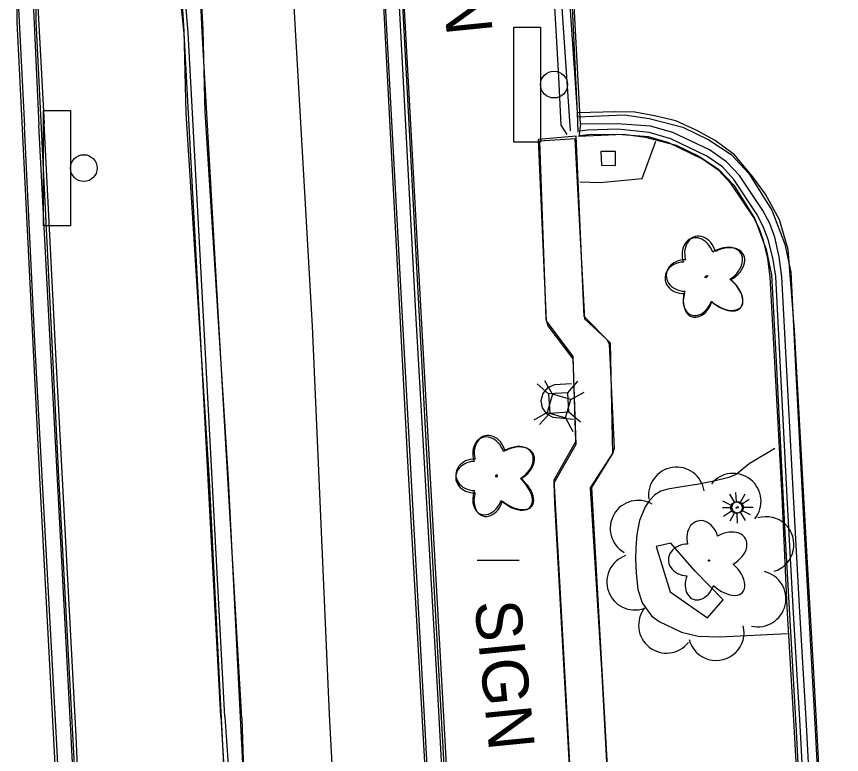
# Model space of a CAD drawing. Extents: x 588843 to 2552415, y 180129 to 269402.
# Drawn here: x 594718.3 to 594826, y 184696.5 to 184792.7 of the extents above; entities that cross this region are included whole.
import ezdxf

# ---------------------------------------------------------------- set-up
doc = ezdxf.new("R2010")
doc.units = 0
for name, color, linetype in [('Default', 7, 'Continuous'), ('E_DWY', 7, 'Continuous'), ('E_LAND_ShrubLine', 7, 'Continuous'), ('E_LAND_TreeLine_P', 7, 'Continuous'), ('E_LAND_Vegetation', 7, 'Continuous'), ('E_LTG', 7, 'Continuous'), ('E_MISCPROP_Planter', 7, 'Continuous'), ('E_PATH_Sidewalk', 7, 'Continuous'), ('E_RDWY_AsphConc', 7, 'Continuous'), ('E_RDWY_C_and_G', 7, 'Continuous'), ('E_RDWY_PavtEdge', 7, 'Continuous'), ('E_SGN', 7, 'Continuous'), ('E_SGN_Text', 7, 'Continuous'), ('E_STRUCT', 7, 'Continuous'), ('E_UTL_AG_Bold', 7, 'Continuous'), ('E_WAL', 7, 'Continuous')]:
    doc.layers.add(name, color=color, linetype=linetype)

# ---------------------------------------------------------------- blocks, each defined once
blk = doc.blocks.new('PED')
at = {"layer": 'Default'}
for p, q in [((-2.5, 2.5), (-5.33, 5.33)), ((2.5, 2.5), (5.33, 5.33)), ((-2.5, -2.5), (-5.33, -5.33)), ((2.5, -2.5), (5.33, -5.33))]:
    blk.add_line(p, q, dxfattribs=at)
blk.add_lwpolyline([(-2.5, -2.5), (2.5, -2.5), (2.5, 2.5), (-2.5, 2.5)], close=True, dxfattribs=at)
blk = doc.blocks.new('LPOL')
at = {"layer": 'Default'}
for p, q in [((-0.75, 1.3), (-2, 3.46)), ((0.75, 1.3), (2, 3.46)), ((-4, 0), (-1.5, 0)), ((1.5, 0), (4, 0)), ((-2, -3.46), (-0.75, -1.3)), ((2, -3.46), (0.75, -1.3))]:
    blk.add_line(p, q, dxfattribs=at)
for radius in [1.5, 1.5, 1.5, 0.125]:
    blk.add_circle((0, 0), radius, dxfattribs=at)
blk = doc.blocks.new('SGN_1')
at = {"layer": 'Default'}
blk.add_lwpolyline([(-3.5, -15), (-10.5, -15), (-10.5, 15), (-3.5, 15)], close=True, dxfattribs=at)
blk.add_circle((0, 0), 3.5, dxfattribs=at)
blk = doc.blocks.new('DTRE_1_1')
at = {"layer": 'Default'}
blk.add_circle((-0.18, 0), 0.183, dxfattribs=at)
for centre, major_axis, ratio in [((-1.87, 5.32), (1.36, -4.98), 0.782863), ((4.06, 2.74), (-5.27, -2.93), 0.691916), ((-5.87, 0.15), (4.93, -0.12), 0.832022), ((3.54, -3.71), (-5.01, 4.58), 0.560249), ((-2.49, -5.24), (1.8, 4.86), 0.716896)]:
    blk.add_ellipse(centre, major_axis=major_axis, ratio=ratio, start_param=1.570796, end_param=4.712389, dxfattribs=at)
blk = doc.blocks.new('LPOL_4')
at = {"layer": 'E_LTG'}
for p, q in [((-2.46, 4.26), (-6.56, 11.36)), ((2.46, 4.26), (6.56, 11.36)), ((-13.12, 0), (-4.92, 0)), ((4.92, 0), (13.12, 0)), ((-6.56, -11.36), (-2.46, -4.26)), ((6.56, -11.36), (2.46, -4.26))]:
    blk.add_line(p, q, dxfattribs=at)
for radius in [4.92, 4.92, 4.92, 0.41]:
    blk.add_circle((0, 0), radius, dxfattribs=at)
blk = doc.blocks.new('DTRE_4')
at = {"layer": 'E_LAND_Vegetation'}
blk.add_circle((-0.6, 0), 0.601, dxfattribs=at)
for centre, major_axis, ratio in [((-6.14, 17.45), (4.46, -16.34), 0.782863), ((13.31, 8.98), (-17.3, -9.61), 0.691916), ((-19.26, 0.5), (16.18, -0.4), 0.832022), ((11.62, -12.16), (-16.44, 15.03), 0.560249), ((-8.18, -17.2), (5.91, 15.93), 0.716896)]:
    blk.add_ellipse(centre, major_axis=major_axis, ratio=ratio, start_param=1.570796, end_param=4.712389, dxfattribs=at)
blk = doc.blocks.new('PED_3')
at = {"layer": 'E_UTL_AG_Bold'}
for p, q in [((-8.2, 8.2), (-17.48, 17.48)), ((8.2, 8.2), (17.48, 17.48)), ((-8.2, -8.2), (-17.48, -17.48)), ((8.2, -8.2), (17.48, -17.48))]:
    blk.add_line(p, q, dxfattribs=at)
blk.add_lwpolyline([(-8.2, -8.2), (8.2, -8.2), (8.2, 8.2), (-8.2, 8.2)], close=True, dxfattribs=at)
blk = doc.blocks.new('SIGN_3')
at = {"layer": 'E_SGN'}
blk.add_text('SIGN', height=39.37, dxfattribs=at).set_placement((-56.13, -19.68))

msp = doc.modelspace()

# ---------------------------------------------------------------- linework, layer by layer
at = {"layer": 'E_DWY'}
for points in [[(594789.01, 184816.25), (594791.51, 184779.58)], [(594823.35, 184688.72), (594822.34, 184707.09), (594821.51, 184721.44), (594820.6, 184737.77), (594819.82, 184751.76), (594819.02, 184762.29), (594817.89, 184766.14), (594816.04, 184769.5), (594814.36, 184771.83), (594812.01, 184774.62), (594809.49, 184776.51), (594807.01, 184777.85), (594804.36, 184779.07), (594801.57, 184779.74), (594799, 184780.2), (594796.53, 184780.25), (594791.54, 184780.11)], [(594791.51, 184779.58), (594797.65, 184779.85), (594800.87, 184779.39), (594805.25, 184778.25), (594808.67, 184776.58), (594811.56, 184774.69), (594813.89, 184772.2), (594816.89, 184767.41), (594818.56, 184762.99), (594819.34, 184759.34), (594819.97, 184746.98), (594821.08, 184725.47), (594822.5, 184700.4)], [(594791.62, 184777.08), (594797.53, 184777.34), (594800.38, 184776.93), (594804.38, 184775.89), (594807.44, 184774.4), (594809.94, 184772.76), (594811.9, 184770.67), (594814.64, 184766.3), (594816.15, 184762.28), (594816.85, 184759.01), (594817.47, 184746.85), (594818.58, 184725.34), (594820.01, 184700.26)], [(594820, 184700.38), (594821.46, 184672.4), (594823.08, 184639.78), (594823.47, 184632.92)], [(594822.5, 184700.51), (594823.95, 184672.53), (594825.57, 184639.92), (594825.96, 184633.06)]]:
    msp.add_lwpolyline(points, dxfattribs=at)
at = {"layer": 'E_LAND_ShrubLine'}
msp.add_lwpolyline([(594803.68, 184724.02), (594801.79, 184723.59), (594803.6, 184717.65), (594808.47, 184714.29), (594810.51, 184716.6), (594806.82, 184720.4)], close=True, dxfattribs=at)
at = {"layer": 'E_LAND_TreeLine_P'}
for centre, start, end in [((594804.44, 184730.28), 8.6203, 188.6203), ((594811.83, 184729.46), 321.1966, 141.1966), ((594799.44, 184725.95), 59.7491, 239.7491), ((594816.12, 184723.82), 286.7654, 106.7654), ((594798.99, 184718.94), 109.1967, 289.1967), ((594815.07, 184716.75), 256.8004, 76.8004), ((594803.14, 184713.31), 141.7812, 321.7812), ((594809.62, 184712.35), 194.2218, 14.2218)]:
    msp.add_arc(centre, 3.64, start, end, dxfattribs=at)
at = {"layer": 'E_MISCPROP_Planter'}
for points in [[(594791.84, 184771.1), (594794.47, 184771.02), (594799.97, 184771.55), (594801.76, 184776.41)], [(594790.76, 184744.79), (594788.51, 184744.65), (594787.62, 184744.26), (594786.99, 184743.52), (594786.74, 184742.58), (594786.74, 184742.58), (594786.91, 184741.65), (594787.47, 184740.88), (594788.3, 184740.42), (594788.3, 184740.42), (594790.99, 184740.19)], [(594817.26, 184736.35), (594813.94, 184734.33), (594812.23, 184732.98), (594812.23, 184732.98), (594811.28, 184732.56), (594811.28, 184732.56), (594809.32, 184732.1), (594809.32, 184732.1), (594807.34, 184731.69), (594807.34, 184731.69), (594805.13, 184731.36), (594805.13, 184731.36), (594803.29, 184731.06), (594803.29, 184731.06), (594802.41, 184730.77), (594801.63, 184730.29), (594801.63, 184730.29), (594800.9, 184729.59), (594800.34, 184728.76), (594800.34, 184728.76), (594799.6, 184726.97), (594799.6, 184726.97), (594799.26, 184725.12), (594799.26, 184725.12), (594799.15, 184723.45), (594799.15, 184723.45), (594799.11, 184721.96), (594799.11, 184721.96), (594799.17, 184720.09), (594799.17, 184720.09), (594799.41, 184717.96), (594799.41, 184717.96), (594799.97, 184716.22), (594799.97, 184716.22), (594801.16, 184714.55), (594801.16, 184714.55), (594802.17, 184713.78), (594802.17, 184713.78), (594805.1, 184712.42), (594805.1, 184712.42), (594807.28, 184711.87), (594807.28, 184711.87), (594810.09, 184711.79), (594810.09, 184711.79), (594818.91, 184712.24)]]:
    msp.add_lwpolyline(points, dxfattribs=at)
at = {"layer": 'E_PATH_Sidewalk'}
for points in [[(594797.74, 184652.91), (594794.94, 184703.55), (594793.4, 184731.28), (594796.14, 184735.68), (594795.81, 184750.1), (594792.41, 184753.56), (594791.37, 184777.06), (594786.45, 184776.63)], [(594792.8, 184652.96), (594790.08, 184703.35), (594788.47, 184732.25), (594791.3, 184737.24), (594790.98, 184748.34), (594787.5, 184752.99), (594786.45, 184776.63)], [(594791.25, 184776.72), (594786.56, 184776.42), (594787.4, 184753.25), (594787.66, 184752.35), (594790.93, 184748.04), (594791.31, 184736.87), (594788.45, 184731.85), (594788.53, 184729.27), (594790.77, 184688.8), (594793.22, 184643.35), (594794.8, 184614.59)], [(594791.18, 184776.71), (594792.42, 184753.24), (594795.34, 184750.57), (594795.67, 184749.96), (594796.29, 184736.37), (594796.13, 184735.8), (594793.18, 184731.22), (594794.7, 184706.82), (594797.33, 184658.05), (594799.1, 184624.16), (594799.83, 184613.6)]]:
    msp.add_lwpolyline(points, dxfattribs=at)
at = {"layer": 'E_RDWY_AsphConc'}
msp.add_lwpolyline([(594791.9, 184778.65), (594790.86, 184798.24), (594790.11, 184817.93)], dxfattribs=at)
msp.add_lwpolyline([(594794.57, 184775.09), (594794.64, 184773.31), (594796.47, 184773.26), (594796.5, 184775.08)], close=True, dxfattribs=at)
at = {"layer": 'E_RDWY_C_and_G'}
for points in [[(594764.27, 184831.13), (594766.46, 184789.1), (594769.36, 184734.71), (594772.55, 184677.72)], [(594766.76, 184831.26), (594768.96, 184789.23), (594771.86, 184734.85), (594775.04, 184677.86)], [(594718.43, 184791.96), (594718.35, 184801.14), (594718.73, 184805.88), (594720.18, 184813.05), (594723.29, 184821.43), (594725.59, 184827.56), (594727.26, 184828.19), (594729.05, 184828.71), (594731.7, 184827.95), (594733.61, 184824.99), (594739.33, 184810.73), (594742.25, 184798.17), (594742.67, 184790.92), (594742.92, 184780.14)], [(594720.93, 184791.98), (594720.85, 184801.05), (594721.21, 184805.53), (594722.59, 184812.36), (594725.63, 184820.55), (594727.54, 184825.62), (594728.05, 184825.82), (594729.05, 184826.11), (594730.11, 184825.8), (594731.38, 184823.83), (594736.94, 184809.98), (594739.76, 184797.81), (594740.17, 184790.82), (594740.42, 184780.08)], [(594777.08, 184633.63), (594775.2, 184633.55), (594774.21, 184652.19), (594771.49, 184702.97), (594768.71, 184753.45), (594765.95, 184803.81)], [(594778.76, 184630.05), (594777.08, 184633.63), (594776.1, 184652.26), (594773.41, 184702.94), (594770.48, 184753.24), (594767.8, 184803.8)], [(594779.34, 184630.27), (594777.65, 184633.73), (594776.77, 184652.29), (594773.99, 184703.02), (594771.16, 184753.32), (594768.38, 184803.92)], [(594747.72, 184701.19), (594744.83, 184751.13), (594742.55, 184790.69), (594742.08, 184801.18)], [(594744.99, 184701.39), (594742.33, 184751.07), (594740.2, 184790.51), (594739.17, 184800.26)], [(594745.54, 184701.35), (594742.89, 184751.17), (594740.76, 184790.55), (594740.21, 184796.97)], [(594718.52, 184795.48), (594719.41, 184778.31)], [(594720.49, 184795.56), (594721.24, 184778.5)], [(594721.06, 184795.63), (594721.96, 184778.71)], [(594724.06, 184683), (594721.37, 184732.51), (594718.42, 184791.96)], [(594726.55, 184683.13), (594723.86, 184732.64), (594720.92, 184792.08)], [(594740.42, 184780.08), (594743.46, 184732.19), (594745.52, 184691.69)], [(594742.92, 184780.24), (594745.96, 184732.33), (594748.01, 184691.82)], [(594724.39, 184682.67), (594723.55, 184698.55), (594720.8, 184749.42), (594719.41, 184778.31)], [(594726.29, 184682.73), (594725.47, 184698.74), (594722.78, 184749.52), (594721.24, 184778.5)], [(594726.83, 184682.74), (594726.13, 184698.83), (594723.43, 184749.56), (594721.96, 184778.71)], [(594823.84, 184653.88), (594821.39, 184700.32), (594820.5, 184715.79), (594819.72, 184730.13), (594818.18, 184758.72), (594817.84, 184761.32), (594817.25, 184763.89), (594817.25, 184763.89), (594816.6, 184765.69), (594815.72, 184767.38), (594815.72, 184767.38), (594812.65, 184771.93), (594812.65, 184771.93), (594810.97, 184773.72), (594810.97, 184773.72), (594808.73, 184775.27), (594808.73, 184775.27), (594803.95, 184777.56), (594803.95, 184777.56), (594801.03, 184778.38), (594801.03, 184778.38), (594796.68, 184778.68), (594796.68, 184778.68), (594791.9, 184778.65), (594791.78, 184777.74), (594791.73, 184777.12)], [(594823.06, 184653.8), (594820.55, 184700.24), (594819.67, 184715.66), (594818.87, 184730.01), (594817.39, 184758.78), (594816.99, 184761.22), (594816.38, 184763.61), (594816.38, 184763.61), (594815.76, 184765.3), (594814.93, 184766.9), (594814.93, 184766.9), (594811.93, 184771.44), (594811.93, 184771.44), (594810.42, 184773.08), (594810.42, 184773.08), (594808.41, 184774.48), (594808.41, 184774.48), (594803.7, 184776.73), (594803.7, 184776.73), (594800.88, 184777.56), (594800.88, 184777.56), (594796.73, 184777.98), (594796.73, 184777.98), (594792.82, 184777.84), (594791.78, 184777.74)], [(594822.37, 184653.72), (594819.8, 184700.18), (594818.89, 184715.65), (594818.21, 184730.08), (594816.65, 184758.75), (594816.34, 184761.12), (594815.81, 184763.45), (594815.81, 184763.45), (594815.23, 184765.07), (594814.45, 184766.6), (594814.45, 184766.6), (594811.56, 184770.87), (594811.56, 184770.87), (594809.95, 184772.59), (594809.95, 184772.59), (594807.85, 184774.06), (594807.85, 184774.06), (594803.46, 184776.2), (594803.46, 184776.2), (594800.79, 184776.97), (594800.79, 184776.97), (594796.77, 184777.29), (594796.77, 184777.29), (594793, 184777.24), (594791.73, 184777.12)], [(594744.99, 184701.39), (594745.56, 184691.72)], [(594745.54, 184701.35), (594746.18, 184691.96)], [(594747.72, 184701.19), (594748.03, 184691.58)]]:
    msp.add_lwpolyline(points, dxfattribs=at)
at = {"layer": 'E_RDWY_PavtEdge'}
msp.add_lwpolyline([(594769.3, 184449.63), (594768.81, 184476.19), (594768.17, 184495.11), (594766.41, 184560.33), (594764.46, 184608.96), (594761.88, 184651.59), (594759.18, 184701.67), (594756.97, 184752.3), (594753.92, 184805.39), (594753.11, 184816.97), (594752.39, 184828.97), (594751.91, 184840.99), (594751.91, 184840.99), (594751.86, 184846.91), (594752.06, 184852.84), (594752.06, 184852.84), (594753.49, 184875.84)], dxfattribs=at)
at = {"layer": 'E_SGN'}
msp.add_line((594778.44, 184721.79), (594783.93, 184721.81), dxfattribs=at)
at = {"layer": 'E_STRUCT'}
msp.add_lwpolyline([(594787.85, 184818.16), (594790.57, 184777.76)], dxfattribs=at)
at = {"layer": 'E_WAL'}
for points in [[(594790.25, 184819.62), (594790.11, 184821.19), (594787.23, 184820.86), (594787.91, 184804.55), (594789.06, 184784.79), (594789.34, 184778.51), (594790.15, 184777.28)], [(594791.61, 184777.61), (594791.54, 184780.11), (594789.8, 184816.73), (594789.89, 184819.23)]]:
    msp.add_lwpolyline(points, dxfattribs=at)

# ---------------------------------------------------------------- block references
at = {"layer": 'E_LAND_Vegetation', "xscale": 0.15240030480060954, "yscale": 0.15240030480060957, "rotation": 3.4338469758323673}
for p in [(594808.34, 184758.7), (594781.04, 184732.72)]:
    msp.add_blockref('DTRE_4', p, dxfattribs=at)
at = {"layer": 'E_LAND_Vegetation', "xscale": 0.5, "yscale": 0.5}
for p in [(594808.5, 184758.82), (594781.06, 184732.84), (594808.78, 184721.74)]:
    msp.add_blockref('DTRE_1_1', p, dxfattribs=at)
at = {"layer": 'E_LTG'}
for name, p, xscale, yscale, rotation in [('LPOL_4', (594812.42, 184728.68), 0.15240030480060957, 0.15240030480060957, 0.8014450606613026), ('LPOL', (594812.25, 184728.63), 0.49999999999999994, 0.5000000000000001, -86.43585136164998)]:
    msp.add_blockref(name, p, dxfattribs=dict(at, xscale=xscale, yscale=yscale, rotation=rotation))
at = {"layer": 'E_SGN', "xscale": 0.5, "yscale": 0.5}
for p in [(594788.46, 184783.8), (594727.13, 184772.9)]:
    msp.add_blockref('SGN_1', p, dxfattribs=at)
at = {"layer": 'E_SGN_Text', "xscale": 0.15240030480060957, "yscale": 0.1524003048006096, "rotation": -84.31519139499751}
for p in [(594776.4, 184801.33), (594781.91, 184708.09)]:
    msp.add_blockref('SIGN_3', p, dxfattribs=at)
at = {"layer": 'E_UTL_AG_Bold'}
for name, p, xscale, yscale, rotation in [('PED_3', (594789.11, 184741.88), 0.1524003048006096, 0.1524003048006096, -15.969778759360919), ('PED', (594789.08, 184742.3), 0.49999999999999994, 0.5000000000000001, -86.43585136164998)]:
    msp.add_blockref(name, p, dxfattribs=dict(at, xscale=xscale, yscale=yscale, rotation=rotation))

doc.saveas('drawing.dxf')
